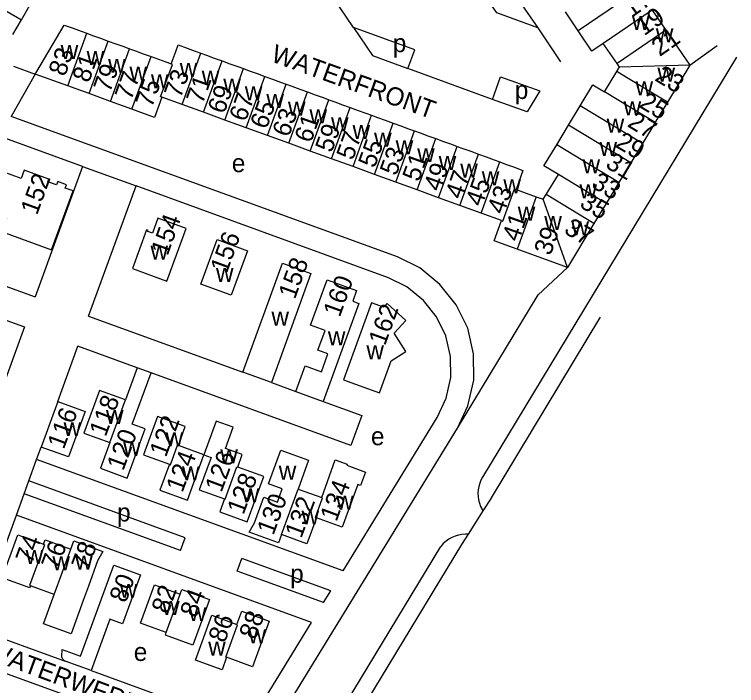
# Model space of a CAD drawing. Extents: x 154320 to 156262, y 382651 to 384180.
# Drawn here: x 156103.4 to 156262.2, y 383033.1 to 383180.7 of the extents above; entities that cross this region are included whole.
import ezdxf

# ---------------------------------------------------------------- set-up
doc = ezdxf.new("R2010")
doc.units = 0
for name, color, linetype in [('BLT_Basislijn', 7, 'Continuous'), ('BLT_Bebouwing', 7, 'Continuous'), ('BLT_Centroide', 7, 'Continuous'), ('BLT_Gemeentegrens', 7, 'Continuous'), ('BLT_Huisnummer', 7, 'Continuous'), ('BLT_Huisnummer_ tussenligend', 7, 'Continuous'), ('BLT_Huisnummer_zonder_bebouwing', 7, 'Continuous'), ('BLT_Onderverdeling_panden', 7, 'Continuous'), ('BLT_Plantopo', 7, 'Continuous'), ('BLT_Straatnaam', 7, 'Continuous')]:
    doc.layers.add(name, color=color, linetype=linetype)

msp = doc.modelspace()

# ---------------------------------------------------------------- linework, layer by layer
at = {"layer": 'BLT_Basislijn'}
for p, q in [((156177.97, 383177.79), (156172.89, 383185.3)), ((156118.43, 383147.22), (156036.57, 383176.99)), ((156218.52, 383177.7), (156223.53, 383170.26)), ((156251.93, 383169.49), (156257.94, 383173.83)), ((156262.22, 383171.24), (156206.38, 383078.95)), ((156103.25, 383169.28), (156108.02, 383167.55)), ((156208.56, 383161.99), (156189.95, 383168.77)), ((156108.02, 383167.55), (156102.73, 383158.25)), ((156118.43, 383147.22), (156108, 383118.56)), ((156118.43, 383147.22), (156130.17, 383142.95)), ((156119.75, 383114.29), (156130.17, 383142.95)), ((156073.69, 383131.02), (156108, 383118.56)), ((156119.75, 383114.29), (156153.65, 383102.04)), ((156099.63, 383114.14), (156105.61, 383111.98)), ((156105.61, 383111.98), (156096.56, 383087.08)), ((156112.94, 383095.57), (156117.36, 383107.71)), ((156159.94, 383099.76), (156165.31, 383097.76)), ((156108.3, 383082.8), (156109.3, 383085.55)), ((156106.6, 383078.1), (156108.3, 383082.8)), ((156175.68, 383058.31), (156108.3, 383082.8)), ((156105.57, 383075.29), (156106.6, 383078.1)), ((156140.99, 383065.6), (156106.6, 383078.1)), ((156103.86, 383070.59), (156105.57, 383075.29)), ((156139.97, 383062.78), (156105.57, 383075.29)), ((156094.81, 383045.68), (156103.86, 383070.59)), ((156168.74, 383047), (156103.86, 383070.59)), ((156139.97, 383062.78), (156140.99, 383065.6)), ((156158.62, 382999.98), (156197.18, 383063.71)), ((156152.43, 383058.25), (156153.45, 383061.07)), ((156173.01, 383053.96), (156153.45, 383061.07)), ((156171.41, 383051.35), (156152.43, 383058.25))]:
    msp.add_line(p, q, dxfattribs=at)
for points in [[(156204.88, 383187.64), (156214.01, 383184.3), (156218.52, 383177.7)], [(156218.52, 383177.7), (156209.49, 383180.97), (156204.88, 383187.64)], [(156189.95, 383168.77), (156191.47, 383172.88), (156177.97, 383177.79)], [(156177.97, 383177.79), (156182.19, 383171.6), (156189.95, 383168.77)], [(156200.85, 383089.67), (156203.15, 383094.62), (156204.46, 383100.24), (156204.4, 383106.02), (156203.12, 383111.67), (156200.54, 383116.84), (156196.98, 383121.3), (156192.54, 383124.94), (156187.68, 383127.36), (156102.73, 383158.25)], [(156175.68, 383058.31), (156196.38, 383092.07), (156198.34, 383096.28), (156199.4, 383100.81), (156199.35, 383105.46), (156198.32, 383110), (156196.25, 383114.16), (156193.35, 383117.79), (156189.75, 383120.74), (156185.65, 383122.78), (156130.17, 383142.95)], [(156218.63, 383119.02), (156225.02, 383125)], [(156200.85, 383089.67), (156218.63, 383119.02)], [(156130.44, 383102.96), (156117.36, 383107.71)], [(156171.32, 383095.57), (156179.79, 383092.46), (156177.4, 383085.88), (156133.47, 383101.84)], [(156147.79, 383003.15), (156200.85, 383089.67)], [(156206.38, 383078.95), (156206.02, 383078.29), (156205.74, 383077.6), (156205.53, 383076.89), (156205.4, 383076.15), (156205.34, 383075.41), (156205.37, 383074.66), (156205.48, 383073.93), (156205.66, 383073.2), (156205.93, 383072.5), (156206.39, 383071.58)], [(156206.39, 383071.58), (156206.43, 383071.52)], [(156203.2, 383066.43), (156202.61, 383066.43), (156201.84, 383066.35), (156201.08, 383066.2), (156200.34, 383065.97), (156199.63, 383065.66), (156198.96, 383065.28), (156198.33, 383064.83), (156197.74, 383064.32), (156197.18, 383063.71)], [(156171.41, 383051.35), (156173.01, 383053.96)], [(156154.6, 383023.94), (156168.74, 383047)], [(156094.81, 383045.68), (156114.6, 383038.49)], [(156150.87, 383017.85), (156092.41, 383039.1)], [(156120.28, 383036.42), (156154.6, 383023.94)]]:
    msp.add_lwpolyline(points, dxfattribs=at)
msp.add_lwpolyline([(156208.56, 383161.99), (156210.34, 383166.95), (156218.95, 383163.84), (156216.15, 383159.22)], close=True, dxfattribs=at)
at = {"layer": 'BLT_Bebouwing'}
for p, q in [((156227.39, 383177.05), (156224.57, 383181.19)), ((156225.25, 383156.3), (156227.84, 383160.57)), ((156222.67, 383152.02), (156225.25, 383156.3)), ((156130.44, 383102.96), (156127.84, 383095.92)), ((156133.47, 383101.84), (156130.44, 383102.96)), ((156159.94, 383099.76), (156153.65, 383102.04)), ((156165.31, 383097.76), (156171.32, 383095.57)), ((156112.94, 383095.57), (156109.3, 383085.55)), ((156145.09, 383083.86), (156139.48, 383085.9)), ((156165.79, 383076.33), (156170.99, 383074.46)), ((156112.15, 383053.11), (156106.97, 383055.03)), ((156120.28, 383036.42), (156114.6, 383038.49))]:
    msp.add_line(p, q, dxfattribs=at)
for points in [[(156104.95, 383179.47), (156106.82, 383182.67)], [(156243.64, 383181.62), (156246.68, 383177.17)], [(156103.08, 383176.26), (156104.95, 383179.47)], [(156108.35, 383168.12), (156114.34, 383178.33), (156114.56, 383178.25)], [(156114.56, 383178.25), (156116.35, 383177.6)], [(156116.35, 383177.6), (156118.1, 383176.97)], [(156118.1, 383176.97), (156119.35, 383176.51)], [(156119.35, 383176.51), (156120.62, 383176.05)], [(156232.91, 383174.29), (156230.43, 383172.6), (156227.39, 383177.05)], [(156246.68, 383177.17), (156251.93, 383169.49)], [(156120.62, 383176.05), (156122.35, 383175.42)], [(156122.35, 383175.42), (156124.06, 383174.81)], [(156124.06, 383174.81), (156125.76, 383174.19)], [(156125.76, 383174.19), (156127.46, 383173.57)], [(156127.46, 383173.57), (156128.75, 383173.1)], [(156128.75, 383173.1), (156130.04, 383172.63)], [(156138.9, 383172.48), (156139.43, 383173.95), (156141.4, 383173.23)], [(156141.4, 383173.23), (156143.14, 383172.6)], [(156235.95, 383169.84), (156232.91, 383174.29)], [(156130.04, 383172.63), (156131.74, 383172.01)], [(156131.74, 383172.01), (156133.46, 383171.39)], [(156133.46, 383171.39), (156136.74, 383170.2)], [(156138.27, 383170.73), (156138.9, 383172.48)], [(156143.14, 383172.6), (156144.39, 383172.15)], [(156144.39, 383172.15), (156145.66, 383171.69)], [(156145.66, 383171.69), (156147.38, 383171.06)], [(156136.74, 383170.2), (156136.94, 383170.13)], [(156136.94, 383170.13), (156137.92, 383169.77)], [(156137.92, 383169.77), (156138.27, 383170.73)], [(156147.38, 383171.06), (156149.08, 383170.44)], [(156149.08, 383170.44), (156150.78, 383169.82)], [(156150.78, 383169.82), (156152.53, 383169.19)], [(156236.48, 383169.06), (156235.95, 383169.84)], [(156152.53, 383169.19), (156153.77, 383168.74)], [(156153.77, 383168.74), (156155.04, 383168.28)], [(156155.04, 383168.28), (156156.77, 383167.65)], [(156235.9, 383168.09), (156236.44, 383168.99)], [(156236.44, 383168.99), (156236.48, 383169.06)], [(156251.93, 383169.49), (156247.02, 383161.36)], [(156108.02, 383167.55), (156108.35, 383168.12)], [(156115.14, 383164.96), (156108.02, 383167.55)], [(156156.77, 383167.65), (156158.48, 383167.02)], [(156158.48, 383167.02), (156160.2, 383166.4)], [(156233.21, 383163.64), (156235.9, 383168.09)], [(156160.2, 383166.4), (156161.93, 383165.77)], [(156161.93, 383165.77), (156163.19, 383165.31)], [(156163.19, 383165.31), (156164.46, 383164.85)], [(156227.84, 383160.57), (156230.64, 383165.2), (156233.21, 383163.64)], [(156119.84, 383163.24), (156115.14, 383164.96)], [(156164.46, 383164.85), (156166.17, 383164.23)], [(156166.17, 383164.23), (156167.88, 383163.61)], [(156167.88, 383163.61), (156169.58, 383162.99)], [(156124.54, 383161.53), (156119.84, 383163.24)], [(156135.82, 383162.48), (156134.2, 383158.02)], [(156140.28, 383160.86), (156135.82, 383162.48)], [(156169.58, 383162.99), (156171.31, 383162.36)], [(156171.31, 383162.36), (156172.58, 383161.9)], [(156172.58, 383161.9), (156173.85, 383161.44)], [(156129.24, 383159.82), (156124.54, 383161.53)], [(156144.97, 383159.15), (156140.28, 383160.86)], [(156173.85, 383161.44), (156175.58, 383160.81)], [(156175.58, 383160.81), (156177.29, 383160.19)], [(156247.02, 383161.36), (156244.72, 383157.57)], [(156134.2, 383158.02), (156129.24, 383159.82)], [(156149.67, 383157.44), (156144.97, 383159.15)], [(156177.29, 383160.19), (156178.99, 383159.57)], [(156178.99, 383159.57), (156180.7, 383158.94)], [(156180.7, 383158.94), (156181.98, 383158.48)], [(156154.38, 383155.73), (156149.67, 383157.44)], [(156181.98, 383158.48), (156183.23, 383158.03)], [(156183.23, 383158.03), (156184.97, 383157.39)], [(156184.97, 383157.39), (156186.68, 383156.77)], [(156244.72, 383157.57), (156244.32, 383156.91)], [(156159.08, 383154.02), (156154.38, 383155.73)], [(156186.68, 383156.77), (156188.37, 383156.16)], [(156188.37, 383156.16), (156190.11, 383155.53)], [(156190.11, 383155.53), (156191.37, 383155.07)], [(156244.32, 383156.91), (156241.53, 383152.29)], [(156163.77, 383152.32), (156159.08, 383154.02)], [(156191.37, 383155.07), (156192.63, 383154.61)], [(156192.63, 383154.61), (156194.36, 383153.98)], [(156194.36, 383153.98), (156196.08, 383153.36)], [(156196.08, 383153.36), (156197.79, 383152.73)], [(156197.79, 383152.73), (156199.52, 383152.1)], [(156168.48, 383150.61), (156163.77, 383152.32)], [(156199.52, 383152.1), (156200.77, 383151.65)], [(156200.77, 383151.65), (156202.01, 383151.2)], [(156202.01, 383151.2), (156203.76, 383150.56)], [(156223.03, 383145.49), (156219.87, 383147.4), (156222.67, 383152.02)], [(156241.53, 383152.29), (156238.94, 383148.02)], [(156173.18, 383148.9), (156168.48, 383150.61)], [(156203.76, 383150.56), (156205.47, 383149.94)], [(156205.47, 383149.94), (156207.18, 383149.32)], [(156207.18, 383149.32), (156208.9, 383148.69)], [(156177.88, 383147.19), (156173.18, 383148.9)], [(156208.9, 383148.69), (156210.18, 383148.23)], [(156210.18, 383148.23), (156211.44, 383147.77)], [(156211.44, 383147.77), (156213.17, 383147.14)], [(156238.94, 383148.02), (156236.35, 383143.74)], [(156182.57, 383145.48), (156177.88, 383147.19)], [(156213.17, 383147.14), (156215.25, 383146.38), (156213.73, 383142.2)], [(156187.27, 383143.78), (156182.57, 383145.48)], [(156220.34, 383141.04), (156223.03, 383145.49)], [(156191.97, 383142.07), (156187.27, 383143.78)], [(156236.35, 383143.74), (156233.56, 383139.12)], [(156196.67, 383140.36), (156191.97, 383142.07)], [(156213.73, 383142.2), (156218.17, 383140.59)], [(156201.37, 383138.65), (156196.67, 383140.36)], [(156218.17, 383140.59), (156219.72, 383140.02)], [(156219.72, 383140.02), (156220.34, 383141.04)], [(156206.07, 383136.94), (156201.37, 383138.65)], [(156233.56, 383139.12), (156230.87, 383134.67)], [(156210.51, 383135.33), (156206.07, 383136.94)], [(156132.78, 383132.96), (156132.85, 383133.15), (156132.5, 383133.27), (156129.42, 383124.82), (156136.96, 383122.04), (156141.16, 383133.61), (156134.96, 383135.88)], [(156134.96, 383135.88), (156133.77, 383132.6), (156132.78, 383132.96)], [(156208.89, 383130.87), (156210.51, 383135.33)], [(156230.87, 383134.67), (156225.02, 383125)], [(156213.96, 383129.02), (156208.89, 383130.87)], [(156225.02, 383125), (156213.96, 383129.02)], [(156153.65, 383102.04), (156162.36, 383125.98), (156168.64, 383123.69), (156159.94, 383099.76)], [(156165.31, 383097.76), (156167.37, 383103.4), (156170.92, 383102.11), (156172.34, 383106.02), (156170.16, 383106.82), (156171.76, 383111.2), (156168.53, 383112.34), (156172.19, 383122.33), (156178.67, 383119.99), (156177.82, 383117.59), (156179.15, 383117.12), (156173.38, 383101.21), (156171.32, 383095.57)], [(156124.43, 383086.53), (156122.37, 383080.9), (156128.25, 383078.75), (156132.18, 383089.56), (156129.35, 383090.59), (156133.47, 383101.84)], [(156127.84, 383095.92), (156122.1, 383098.01), (156118.68, 383088.6), (156124.43, 383086.53)], [(156112.94, 383095.57), (156118.95, 383093.39), (156115.33, 383083.38), (156109.3, 383085.55)], [(156139.48, 383085.9), (156140.99, 383090.07), (156134.92, 383092.28), (156131.83, 383083.82), (156137.52, 383081.76)], [(156152.52, 383081.14), (156153.52, 383083.93), (156149.84, 383085.26), (156151.54, 383089.91), (156147.8, 383091.27), (156145.09, 383083.86)], [(156162.13, 383066.32), (156161.48, 383064.53), (156155.05, 383066.86), (156156.21, 383068.92), (156158.24, 383074.53), (156161.26, 383073.43), (156162.32, 383076.35), (156159.31, 383077.44), (156162.01, 383084.87), (156168.11, 383082.65), (156165.79, 383076.33)], [(156137.52, 383081.76), (156135.43, 383076.05), (156141.46, 383073.89), (156145.09, 383083.86)], [(156145.09, 383083.86), (156146.66, 383083.29), (156144.06, 383076.18), (156149.63, 383074.17)], [(156170.99, 383074.46), (156173.97, 383082.72), (156176.58, 383081.78), (156176.5, 383081.54), (156180.62, 383080.05), (156179.56, 383077.12), (156178.91, 383077.35), (156175.5, 383067.94), (156169.82, 383070)], [(156149.63, 383074.17), (156148.58, 383071.28), (156154.6, 383069.09), (156158.25, 383079.1), (156152.52, 383081.14)], [(156169.82, 383070), (156167.75, 383064.29), (156162.13, 383066.32)], [(156106.97, 383055.03), (156106.81, 383054.6), (156100.73, 383056.83), (156104.15, 383066.23), (156109.82, 383064.17)], [(156109.82, 383064.17), (156110.2, 383065.18), (156115.8, 383063.14)], [(156115.8, 383063.14), (156116.46, 383064.95), (156122.89, 383062.6), (156121.73, 383060.51), (156119.72, 383054.97), (156118.65, 383052.01), (156115.91, 383044.51), (156109.85, 383046.73), (156112.15, 383053.11)], [(156114.6, 383038.49), (156114.44, 383038.57), (156114.21, 383038.75), (156114.05, 383038.96), (156113.97, 383039.09), (156113.9, 383039.25), (156113.85, 383039.42), (156113.83, 383039.6), (156113.89, 383041.08), (156117.99, 383039.6), (156125.27, 383059.61), (156131.14, 383057.49), (156127.22, 383046.66), (156124.4, 383047.69), (156120.28, 383036.42)], [(156136.81, 383044.76), (156131.14, 383046.83), (156134.23, 383055.3), (156139.89, 383053.23)], [(156139.89, 383053.23), (156140.27, 383054.26), (156146.29, 383052.04), (156142.63, 383042.03), (156136.62, 383044.22), (156136.81, 383044.76)], [(156152.36, 383046.56), (156153.41, 383049.46), (156159.44, 383047.28), (156155.79, 383037.25), (156150.08, 383039.33)], [(156150.08, 383039.33), (156149.08, 383036.59), (156143.21, 383038.72), (156146.81, 383048.6), (156152.36, 383046.56)]]:
    msp.add_lwpolyline(points, dxfattribs=at)
for points in [[(156148, 383131.15), (156154.67, 383128.72), (156151.12, 383118.97), (156144.45, 383121.39)], [(156181.92, 383117.25), (156175.76, 383100.35), (156183.68, 383097.47), (156186.25, 383104.53), (156189.47, 383106.53), (156186.96, 383110.56), (156189.52, 383113.35), (156185.36, 383117.13), (156184.58, 383116.27)]]:
    msp.add_lwpolyline(points, close=True, dxfattribs=at)
at = {"layer": 'BLT_Gemeentegrens'}
for points in [[(156232.25, 383114.14), (156232.09, 383113.86), (156208.25, 383074.4), (156208.23, 383074.35), (156206.43, 383071.52)], [(156206.43, 383071.52), (156203.2, 383066.43)], [(156203.2, 383066.43), (156201.72, 383064.1), (156137.57, 382958.26), (156108.02, 382909.51), (156099.04, 382896.48), (156097.72, 382901.18)]]:
    msp.add_lwpolyline(points, dxfattribs=at)
at = {"layer": 'BLT_Onderverdeling_panden'}
for p, q in [((156124.43, 383086.53), (156127.84, 383095.92)), ((156162.13, 383066.32), (156165.79, 383076.33)), ((156112.15, 383053.11), (156115.8, 383063.14)), ((156136.81, 383044.76), (156139.89, 383053.23))]:
    msp.add_line(p, q, dxfattribs=at)
for points in [[(156093.21, 383186.32), (156104.95, 383179.47)], [(156240.6, 383186.08), (156227.39, 383177.05)], [(156243.64, 383181.62), (156232.91, 383174.29)], [(156115.14, 383164.96), (156119.35, 383176.51)], [(156246.68, 383177.17), (156235.95, 383169.84)], [(156119.84, 383163.24), (156124.06, 383174.81)], [(156124.54, 383161.53), (156128.75, 383173.1)], [(156129.24, 383159.82), (156133.46, 383171.39)], [(156140.28, 383160.86), (156144.39, 383172.15)], [(156144.97, 383159.15), (156149.08, 383170.44)], [(156135.82, 383162.48), (156135.58, 383162.57), (156138.16, 383169.68), (156137.92, 383169.77)], [(156149.67, 383157.44), (156153.77, 383168.74)], [(156251.93, 383169.49), (156236.48, 383169.06)], [(156154.38, 383155.73), (156158.48, 383167.02)], [(156238.02, 383166.8), (156235.9, 383168.09)], [(156247.02, 383161.36), (156238.02, 383166.8)], [(156159.08, 383154.02), (156163.19, 383165.31)], [(156163.77, 383152.32), (156167.88, 383163.61)], [(156244.32, 383156.91), (156233.21, 383163.64)], [(156168.48, 383150.61), (156172.58, 383161.9)], [(156241.53, 383152.29), (156227.84, 383160.57)], [(156173.18, 383148.9), (156177.29, 383160.19)], [(156177.88, 383147.19), (156181.98, 383158.48)], [(156182.57, 383145.48), (156186.68, 383156.77)], [(156238.94, 383148.02), (156225.25, 383156.3)], [(156187.27, 383143.78), (156191.37, 383155.07)], [(156191.97, 383142.07), (156196.08, 383153.36)], [(156196.67, 383140.36), (156200.77, 383151.65)], [(156236.35, 383143.74), (156222.67, 383152.02)], [(156201.37, 383138.65), (156205.47, 383149.94)], [(156206.07, 383136.94), (156210.18, 383148.23)], [(156233.56, 383139.12), (156223.03, 383145.49)], [(156210.51, 383135.33), (156210.83, 383135.21), (156213.41, 383142.32), (156213.73, 383142.2)], [(156218.17, 383140.59), (156213.96, 383129.02)], [(156225.02, 383125), (156219.72, 383140.02)], [(156230.87, 383134.67), (156220.34, 383141.04)], [(156137.52, 383081.76), (156137.71, 383081.68), (156139.28, 383085.97), (156139.48, 383085.9)], [(156149.63, 383074.17), (156149.79, 383074.12), (156152.36, 383081.2), (156152.52, 383081.14)], [(156169.82, 383070), (156169.62, 383070.07), (156171.19, 383074.39), (156170.99, 383074.46)], [(156109.82, 383064.17), (156110.04, 383064.09), (156106.76, 383055.1), (156106.97, 383055.03)], [(156150.08, 383039.33), (156149.93, 383039.38), (156152.51, 383046.5), (156152.36, 383046.56)]]:
    msp.add_lwpolyline(points, dxfattribs=at)
at = {"layer": 'BLT_Plantopo'}
msp.add_lwpolyline([(156116.31, 383141.85), (156114.58, 383142.48), (156114.85, 383143.22), (156112.95, 383143.92), (156112.68, 383143.19), (156110.8, 383143.88), (156111, 383144.44), (156105.58, 383146.43), (156104.91, 383144.6), (156100.93, 383146.04), (156097.6, 383137.35), (156101.68, 383135.83), (156100.62, 383132.94), (156111.55, 383128.92)], close=True, dxfattribs=at)

# ---------------------------------------------------------------- texts
at = {"layer": 'BLT_Centroide'}
for s, p in [('w', (156239.22, 383177.26)), ('w', (156244.47, 383174.51)), ('p', (156186.63, 383172.36)), ('w', (156113.6, 383170.83)), ('w', (156119.3, 383169.51)), ('w', (156124.02, 383167.82)), ('w', (156139.77, 383166.93)), ('w', (156128.72, 383166.11)), ('w', (156144.61, 383165.19)), ('w', (156244.83, 383165.85)), ('w', (156133.44, 383164.43)), ('w', (156149.35, 383163.49)), ('p', (156213.46, 383162.07)), ('w', (156240, 383162.88)), ('w', (156154.08, 383161.79)), ('w', (156158.82, 383160.08)), ('w', (156163.57, 383158.38)), ('w', (156237.38, 383158.47)), ('w', (156168.3, 383156.69)), ('w', (156173.04, 383154.97)), ('w', (156233.65, 383154.66)), ('w', (156177.77, 383153.29)), ('w', (156182.51, 383151.57)), ('w', (156187.26, 383149.88)), ('w', (156232.08, 383149.57)), ('w', (156191.99, 383148.18)), ('w', (156196.72, 383146.47)), ('e', (156151.23, 383145.99)), ('w', (156201.46, 383144.77)), ('w', (156228.35, 383145.76)), ('w', (156206.19, 383143.07)), ('w', (156210.93, 383141.36)), ('w', (156227.68, 383140.22)), ('w', (156214.1, 383135.33)), ('w', (156219.94, 383133.24)), ('w', (156225.9, 383132.07)), ('w', (156133.35, 383126.76)), ('w', (156147.74, 383121.86)), ('w', (156159.94, 383112.24)), ('w', (156172.35, 383107.94)), ('w', (156180.82, 383104.86)), ('w', (156123.55, 383090.61)), ('w', (156114.23, 383087.95)), ('e', (156181.83, 383085.95)), ('w', (156136.67, 383085.73)), ('w', (156127.34, 383083.61)), ('w', (156148.69, 383081.97)), ('w', (156140.28, 383078.25)), ('w', (156161.55, 383078.36)), ('w', (156153.42, 383073.42)), ('w', (156174.16, 383071.78)), ('w', (156166.55, 383068.53)), ('w', (156105.89, 383059.84)), ('w', (156111.78, 383058.45)), ('w', (156116.78, 383058.62)), ('w', (156126.59, 383052.41)), ('w', (156135.89, 383048.67)), ('w', (156141.77, 383047.28)), ('w', (156154.88, 383042.38)), ('w', (156146.03, 383039.73)), ('e', (156129.67, 383038.53))]:
    msp.add_text(s, height=4, dxfattribs=at).set_placement(p)
for p in [(156125.99, 383069.21), (156164.05, 383055.74)]:
    msp.add_text('p', height=4, rotation=359.5, dxfattribs=at).set_placement(p)
at = {"layer": 'BLT_Huisnummer'}
for s, rotation, p in [('17', 35.2347, (156239.08, 383179.8)), ('21', 35.2347, (156245.32, 383171.27)), ('83', 70.2347, (156114.54, 383166.85)), ('79', 70.2347, (156124.42, 383163.3)), ('23', 329.2347, (156244.02, 383166.24)), ('71', 70.2347, (156144.82, 383160.78)), ('75', 70.2347, (156133.66, 383159.98)), ('67', 70.2347, (156154.27, 383156.9)), ('63', 70.2347, (156163.75, 383153.5)), ('27', 329.2347, (156237.99, 383156.14)), ('59', 70.2347, (156173.19, 383150.1)), ('55', 70.2347, (156182.64, 383146.71)), ('51', 70.2347, (156192.36, 383143.69)), ('31', 329.2347, (156233.17, 383147.13)), ('47', 70.2347, (156201.76, 383139.82)), ('43', 70.2347, (156211, 383136.51)), ('154', 70.325, (156137.1, 383127.43)), ('37', 329.2347, (156224.04, 383132.71)), ('39', 70.2347, (156221.3, 383127.47)), ('156', 70.0191, (156150.12, 383123.57)), ('158', 70.0191, (156165.1, 383117.89)), ('160', 70.0191, (156174.96, 383113.93)), ('162', 70.0191, (156184.91, 383107.67)), ('116', 69.5777, (156114.28, 383084.89)), ('120', 69.5777, (156127.35, 383080.17)), ('124', 69.5777, (156140.37, 383075.38)), ('128', 69.5777, (156153.79, 383070.51)), ('134', 69.5777, (156174.24, 383068.99)), ('74', 69.5777, (156107.26, 383059.68)), ('80', 69.5777, (156127.91, 383051.12)), ('84', 69.5777, (156143.43, 383047.83)), ('88', 69.5777, (156156.42, 383043.04))]:
    msp.add_text(s, height=4, rotation=rotation, dxfattribs=at).set_placement(p)
at = {"layer": 'BLT_Huisnummer_ tussenligend'}
for s, rotation, p in [('19', 35.2347, (156241.89, 383175.83)), ('81', 70.2347, (156119.79, 383165.45)), ('77', 70.2347, (156129.12, 383161.6)), ('73', 70.2347, (156139.96, 383162.06)), ('69', 70.2347, (156149.52, 383158.61)), ('25', 329.2347, (156240.55, 383160.41)), ('65', 70.2347, (156158.88, 383155.25)), ('61', 70.2347, (156168.62, 383152.23)), ('57', 70.2347, (156177.84, 383148.42)), ('29', 329.2347, (156235.33, 383151.66)), ('53', 70.2347, (156187.39, 383145)), ('49', 70.2347, (156197.03, 383141.53)), ('45', 70.2347, (156206.21, 383138.23)), ('33', 329.2347, (156230.06, 383142.79)), ('35', 329.2347, (156227.47, 383138.44)), ('41', 70.2347, (156214.28, 383130.48)), ('118', 69.5777, (156123.49, 383087.65)), ('122', 69.5777, (156136.74, 383083.15)), ('126', 69.5777, (156148.94, 383075.4)), ('130', 69.5777, (156160.36, 383065.99)), ('132', 69.5777, (156166.51, 383065.34)), ('76', 69.5777, (156112.93, 383058.37)), ('78', 69.5777, (156119.54, 383058.31)), ('82', 69.5777, (156137.16, 383048.69)), ('86', 69.5777, (156149.66, 383042.32))]:
    msp.add_text(s, height=4, rotation=rotation, dxfattribs=at).set_placement(p)
at = {"layer": 'BLT_Huisnummer_zonder_bebouwing'}
msp.add_text('152', height=4, rotation=70.0195, dxfattribs=at).set_placement((156108.4, 383136.38))
at = {"layer": 'BLT_Straatnaam'}
for s, rotation, p in [('WATERFRONT', 340.2347, (156159.61, 383170.39)), ('WATERWERELD', 339.5777, (156097.07, 383039.21))]:
    msp.add_text(s, height=4, rotation=rotation, dxfattribs=at).set_placement(p)

doc.saveas('drawing.dxf')
